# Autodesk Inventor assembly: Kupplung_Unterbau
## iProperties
Created: 2003-04
Part Number: Kupplung_Unterbau
Document SubType Name: Baugruppe
Designer: Administrator
Control State: 0
Master: False
Checked Out: False
Shininess: 20.0
Angle Display Precision: 2
Document Length Units: 11269
Document Angle Units: 11279
Document Time Units: 11290
Document Mass Units: 11283
Document Length Units Precision: 3
Document Angle Units Precision: 2
Density: 0.0
Volumn: 0.0
Area: 0.0
PropertySet Name: Model Information
Author: Administrator
